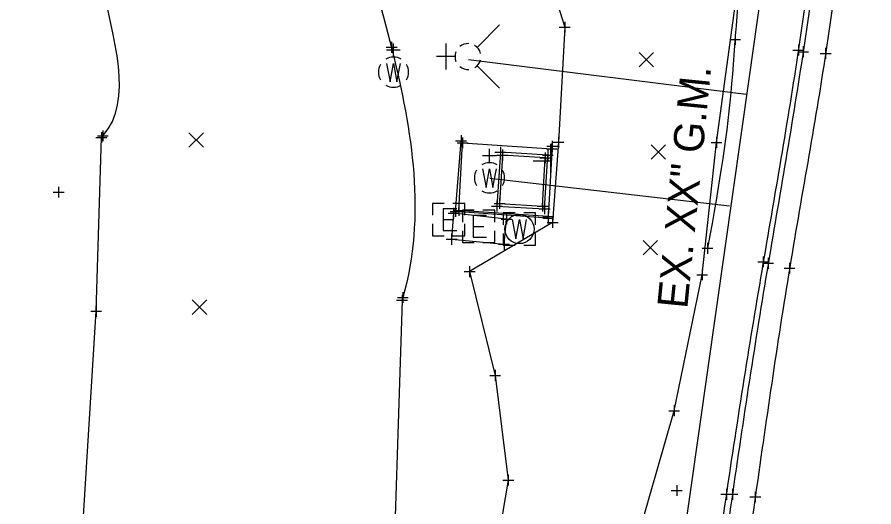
# Model space of a CAD drawing. Extents: x 1324089 to 1329959, y 459099 to 462017.
# Drawn here: x 1324630.8 to 1324710.1, y 459307.9 to 459353.2 of the extents above; entities that cross this region are included whole.
import ezdxf

# ---------------------------------------------------------------- set-up
doc = ezdxf.new("R2010")
doc.units = 0
for name, color, linetype in [('Default', 7, 'Continuous'), ('DR_X_Elev_Flow', 7, 'Continuous'), ('PM_X_Surveyed_Line', 7, 'Continuous'), ('PV_X_Curb', 7, 'Continuous'), ('PV_X_EOP', 7, 'Continuous'), ('RD_X_Concrete_Pad', 7, 'Continuous'), ('SN_X_Public', 7, 'Continuous'), ('SV_X_Break_Lines', 7, 'Continuous'), ('SV_X_Random_Point', 7, 'Continuous'), ('SV_X_Shot_Marker', 7, 'Continuous'), ('UT_X_Electric_Cells', 7, 'Continuous'), ('UT_X_Gas', 7, 'Continuous'), ('UT_X_Gas_Text', 7, 'Continuous'), ('UT_X_Water', 7, 'Continuous'), ('UT_X_Water_Cells', 7, 'Continuous')]:
    doc.layers.add(name, color=color, linetype=linetype)

msp = doc.modelspace()

# ---------------------------------------------------------------- linework, layer by layer
at = {"layer": 'Default'}
for points in [[(1324679.928, 459340.43), (1324675.526, 459340.713), (1324675.203, 459335.709), (1324679.624, 459335.463)], [(1324679.686, 459340.183), (1324675.715, 459340.448), (1324675.459, 459335.961), (1324679.444, 459335.727)]]:
    msp.add_lwpolyline(points, close=True, dxfattribs=at)
at = {"layer": 'DR_X_Elev_Flow'}
for p, q in [((1324634.62, 459337.501), (1324634.62, 459336.501)), ((1324634.12, 459337.001), (1324635.12, 459337.001)), ((1324634.62, 459337.001), (1324634.62, 459337.001))]:
    msp.add_line(p, q, dxfattribs=at)
at = {"layer": 'PM_X_Surveyed_Line'}
msp.add_open_spline([(1324720.827, 459365.006), (1324717.359, 459354.415), (1324715.896, 459334.744), (1324710.688, 459307.465), (1324707.684, 459283.27), (1324704.594, 459259.477), (1324702.801, 459238.335), (1324702.051, 459224.842), (1324701.816, 459219.293)], degree=3, dxfattribs=at)
at = {"layer": 'PV_X_Curb'}
for points in [[(1324554.609, 459526.256), (1324562.727, 459523.451), (1324573.614, 459507.995), (1324595.634, 459494.274), (1324618.058, 459478.412), (1324642.018, 459464.013), (1324665.498, 459452.566), (1324685.244, 459441.867), (1324699.443, 459427.92), (1324705.383, 459409.506), (1324706.272, 459390.25), (1324706.235, 459370.345), (1324703.79, 459350.238), (1324700.16, 459329.847), (1324696.79, 459308.111), (1324693.792, 459284.881), (1324690.959, 459260.876), (1324689.322, 459239.145), (1324688.41, 459225.434), (1324688.071, 459219.66)], [(1324554.405, 459525.774), (1324560.163, 459519.511), (1324574.45, 459509.18), (1324595.041, 459493.357), (1324617.898, 459478.11), (1324641.765, 459463.536), (1324665.205, 459452.03), (1324684.981, 459441.522), (1324698.948, 459427.624), (1324704.887, 459409.371), (1324705.692, 459390.232), (1324705.74, 459370.396), (1324703.348, 459350.363), (1324699.706, 459329.937), (1324696.22, 459308.214), (1324693.202, 459284.97), (1324690.537, 459260.981), (1324688.845, 459239.232), (1324687.9, 459225.509), (1324687.541, 459219.732)]]:
    msp.add_open_spline(points, degree=3, dxfattribs=at)
at = {"layer": 'PV_X_EOP'}
msp.add_open_spline([(1324556.157, 459527.565), (1324561.482, 459521.009), (1324576.429, 459511.53), (1324596.286, 459495.041), (1324619.321, 459480.244), (1324643.042, 459465.698), (1324666.449, 459454.069), (1324686.657, 459443.463), (1324700.989, 459428.912), (1324707.445, 459410.05), (1324708.191, 459390.355), (1324708.255, 459370.269), (1324705.916, 459350.006), (1324702.088, 459329.589), (1324698.992, 459307.797), (1324695.704, 459284.611), (1324693.286, 459260.576), (1324691.164, 459238.914), (1324690.346, 459225.303), (1324690.06, 459219.552)], degree=3, dxfattribs=at)
at = {"layer": 'RD_X_Concrete_Pad'}
for points in [[(1324679.966, 459334.754), (1324671.683, 459335.326), (1324672.034, 459341.579), (1324680.292, 459341.024), (1324680.315, 459341.259)], [(1324675.87, 459332.182), (1324676.096, 459334.51), (1324671.187, 459335.066), (1324671.016, 459332.644)]]:
    msp.add_lwpolyline(points, close=True, dxfattribs=at)
at = {"layer": 'SN_X_Public'}
for p, q in [((1324680.167, 459341.492), (1324680.167, 459338.292)), ((1324680.167, 459339.892), (1324678.567, 459339.892)), ((1324680.166, 459339.893), (1324680.166, 459339.893))]:
    msp.add_line(p, q, dxfattribs=at)
at = {"layer": 'SV_X_Break_Lines'}
for p, q in [((1324638.576, 459342.074), (1324638.714, 459342.227)), ((1324638.099, 459325.974), (1324638.576, 459342.074)), ((1324666.49, 459327.249), (1324666.423, 459327.011)), ((1324666.423, 459327.011), (1324665.662, 459303.052)), ((1324636.69, 459303.119), (1324638.099, 459325.974))]:
    msp.add_line(p, q, dxfattribs=at)
for points in [[(1324541.094, 459511.122), (1324561.978, 459492.743), (1324584.525, 459475.422), (1324605.248, 459461.382), (1324621.289, 459450.829), (1324632.107, 459444.104), (1324650.067, 459430.271), (1324666.204, 459410.058), (1324661.436, 459407.256), (1324665.741, 459392.416), (1324674.496, 459384.978), (1324677.71, 459376.688), (1324678.667, 459361.235), (1324681.487, 459352.293), (1324680.906, 459341.626), (1324680.368, 459334.206), (1324672.683, 459329.647), (1324675.043, 459320.041), (1324676.262, 459310.343), (1324675.179, 459303.964)], [(1324679.945, 459334.597), (1324671.367, 459335.214), (1324671.888, 459341.777)]]:
    msp.add_lwpolyline(points, dxfattribs=at)
for points in [[(1324640.512, 459459.521), (1324647.089, 459455.926), (1324657.022, 459448.614), (1324672.404, 459438.049), (1324688.497, 459430.408), (1324692.817, 459411.585), (1324698.272, 459395.281), (1324701.471, 459375.962), (1324697.719, 459361.699), (1324697.169, 459346.683), (1324695.905, 459338.224), (1324694.71, 459331.809)], [(1324562.077, 459396.515), (1324566.564, 459401.675), (1324579.241, 459409.429), (1324602.412, 459413.502), (1324625.669, 459407.067), (1324650.217, 459397.51), (1324658.543, 459372.548), (1324666.101, 459350.529), (1324668.645, 459334.822), (1324666.49, 459327.249)], [(1324638.714, 459342.227), (1324641.647, 459345.482), (1324637.721, 459357.192), (1324636.716, 459371.71), (1324623.652, 459387.374), (1324602.817, 459386.761), (1324580.6, 459381.005), (1324574.74, 459367.801), (1324573.351, 459359.374)]]:
    msp.add_open_spline(points, degree=3, dxfattribs=at)
at = {"layer": 'SV_X_Random_Point'}
for p, q in [((1324688.371, 459348.606), (1324689.704, 459349.941)), ((1324688.371, 459349.941), (1324689.704, 459348.606)), ((1324646.693, 459341.171), (1324648.026, 459342.506)), ((1324646.693, 459342.506), (1324648.026, 459341.171)), ((1324689.492, 459340.058), (1324690.825, 459341.393)), ((1324689.492, 459341.393), (1324690.825, 459340.058)), ((1324688.756, 459331.198), (1324690.089, 459332.533)), ((1324688.756, 459332.533), (1324690.089, 459331.198)), ((1324646.996, 459325.69), (1324648.33, 459327.025)), ((1324646.996, 459327.025), (1324648.33, 459325.69))]:
    msp.add_line(p, q, dxfattribs=at)
at = {"layer": 'SV_X_Shot_Marker'}
for p, q in [((1324681.487, 459352.793), (1324681.487, 459351.793)), ((1324680.987, 459352.293), (1324681.987, 459352.293)), ((1324681.487, 459352.293), (1324681.487, 459352.293)), ((1324697.279, 459351.654), (1324697.279, 459350.654)), ((1324665.457, 459350.929), (1324665.457, 459349.929)), ((1324696.779, 459351.154), (1324697.779, 459351.154)), ((1324697.279, 459351.154), (1324697.279, 459351.154)), ((1324664.957, 459350.429), (1324665.957, 459350.429)), ((1324665.457, 459350.429), (1324665.457, 459350.429)), ((1324702.622, 459350.166), (1324703.622, 459350.166)), ((1324703.122, 459350.666), (1324703.122, 459349.666)), ((1324703.122, 459350.166), (1324703.122, 459350.166)), ((1324703.569, 459350.519), (1324703.569, 459349.519)), ((1324705.651, 459350.362), (1324705.651, 459349.362)), ((1324703.069, 459350.019), (1324704.069, 459350.019)), ((1324703.569, 459350.019), (1324703.569, 459350.019)), ((1324705.151, 459349.862), (1324706.151, 459349.862)), ((1324705.651, 459349.862), (1324705.651, 459349.862)), ((1324638.214, 459342.227), (1324639.214, 459342.227)), ((1324638.576, 459342.574), (1324638.576, 459341.574)), ((1324638.714, 459342.727), (1324638.714, 459341.727)), ((1324638.714, 459342.227), (1324638.714, 459342.227)), ((1324671.888, 459342.277), (1324671.888, 459341.277)), ((1324680.906, 459342.126), (1324680.906, 459341.126)), ((1324695.549, 459342.119), (1324695.549, 459341.119)), ((1324638.076, 459342.074), (1324639.076, 459342.074)), ((1324638.576, 459342.074), (1324638.576, 459342.074)), ((1324671.388, 459341.777), (1324672.388, 459341.777)), ((1324671.534, 459341.579), (1324672.534, 459341.579)), ((1324671.888, 459341.777), (1324671.888, 459341.777)), ((1324672.034, 459342.079), (1324672.034, 459341.079)), ((1324672.034, 459341.579), (1324672.034, 459341.579)), ((1324680.292, 459341.524), (1324680.292, 459340.524)), ((1324680.315, 459341.759), (1324680.315, 459340.759)), ((1324680.406, 459341.626), (1324681.406, 459341.626)), ((1324680.906, 459341.626), (1324680.906, 459341.626)), ((1324695.049, 459341.619), (1324696.049, 459341.619)), ((1324695.549, 459341.619), (1324695.549, 459341.619)), ((1324675.026, 459340.713), (1324676.026, 459340.713)), ((1324675.526, 459341.213), (1324675.526, 459340.213)), ((1324675.526, 459340.713), (1324675.526, 459340.713)), ((1324675.715, 459340.948), (1324675.715, 459339.948)), ((1324679.686, 459340.683), (1324679.686, 459339.683)), ((1324679.792, 459341.024), (1324680.792, 459341.024)), ((1324679.815, 459341.259), (1324680.815, 459341.259)), ((1324679.928, 459340.93), (1324679.928, 459339.93)), ((1324680.292, 459341.024), (1324680.292, 459341.024)), ((1324680.315, 459341.259), (1324680.315, 459341.259)), ((1324675.215, 459340.448), (1324676.215, 459340.448)), ((1324675.715, 459340.448), (1324675.715, 459340.448)), ((1324679.186, 459340.183), (1324680.186, 459340.183)), ((1324679.428, 459340.43), (1324680.428, 459340.43)), ((1324679.686, 459340.183), (1324679.686, 459340.183)), ((1324679.928, 459340.43), (1324679.928, 459340.43)), ((1324671.683, 459335.826), (1324671.683, 459334.826)), ((1324674.959, 459335.961), (1324675.959, 459335.961)), ((1324675.203, 459336.209), (1324675.203, 459335.209)), ((1324675.459, 459336.461), (1324675.459, 459335.461)), ((1324675.459, 459335.961), (1324675.459, 459335.961)), ((1324679.444, 459336.227), (1324679.444, 459335.227)), ((1324679.624, 459335.963), (1324679.624, 459334.963)), ((1324670.687, 459335.066), (1324671.687, 459335.066)), ((1324670.867, 459335.214), (1324671.867, 459335.214)), ((1324671.183, 459335.326), (1324672.183, 459335.326)), ((1324671.187, 459335.566), (1324671.187, 459334.566)), ((1324671.187, 459335.066), (1324671.187, 459335.066)), ((1324671.367, 459335.714), (1324671.367, 459334.714)), ((1324671.367, 459335.214), (1324671.367, 459335.214)), ((1324671.683, 459335.326), (1324671.683, 459335.326)), ((1324674.703, 459335.709), (1324675.703, 459335.709)), ((1324675.203, 459335.709), (1324675.203, 459335.709)), ((1324676.096, 459335.01), (1324676.096, 459334.01)), ((1324678.944, 459335.727), (1324679.944, 459335.727)), ((1324679.124, 459335.463), (1324680.124, 459335.463)), ((1324679.444, 459335.727), (1324679.444, 459335.727)), ((1324679.624, 459335.463), (1324679.624, 459335.463)), ((1324679.945, 459335.097), (1324679.945, 459334.097)), ((1324679.966, 459335.254), (1324679.966, 459334.254)), ((1324675.596, 459334.51), (1324676.596, 459334.51)), ((1324676.096, 459334.51), (1324676.096, 459334.51)), ((1324679.445, 459334.597), (1324680.445, 459334.597)), ((1324679.466, 459334.754), (1324680.466, 459334.754)), ((1324679.868, 459334.206), (1324680.868, 459334.206)), ((1324679.945, 459334.597), (1324679.945, 459334.597)), ((1324679.966, 459334.754), (1324679.966, 459334.754)), ((1324680.368, 459334.706), (1324680.368, 459333.706)), ((1324680.368, 459334.206), (1324680.368, 459334.206)), ((1324670.516, 459332.644), (1324671.516, 459332.644)), ((1324671.016, 459333.144), (1324671.016, 459332.144)), ((1324671.016, 459332.644), (1324671.016, 459332.644)), ((1324675.87, 459332.682), (1324675.87, 459331.682)), ((1324675.37, 459332.182), (1324676.37, 459332.182)), ((1324675.87, 459332.182), (1324675.87, 459332.182)), ((1324694.21, 459331.809), (1324695.21, 459331.809)), ((1324694.71, 459332.309), (1324694.71, 459331.309)), ((1324694.71, 459331.809), (1324694.71, 459331.809)), ((1324699.873, 459331.064), (1324699.873, 459330.064)), ((1324699.373, 459330.564), (1324700.373, 459330.564)), ((1324699.834, 459330.419), (1324700.834, 459330.419)), ((1324699.873, 459330.564), (1324699.873, 459330.564)), ((1324700.334, 459330.919), (1324700.334, 459329.919)), ((1324700.334, 459330.419), (1324700.334, 459330.419)), ((1324702.307, 459330.474), (1324702.307, 459329.474)), ((1324672.183, 459329.647), (1324673.183, 459329.647)), ((1324672.683, 459330.147), (1324672.683, 459329.147)), ((1324672.683, 459329.647), (1324672.683, 459329.647)), ((1324694.222, 459329.849), (1324694.222, 459328.849)), ((1324701.807, 459329.974), (1324702.807, 459329.974)), ((1324702.307, 459329.974), (1324702.307, 459329.974)), ((1324693.722, 459329.349), (1324694.722, 459329.349)), ((1324694.222, 459329.349), (1324694.222, 459329.349)), ((1324665.99, 459327.249), (1324666.99, 459327.249)), ((1324666.423, 459327.511), (1324666.423, 459326.511)), ((1324666.49, 459327.749), (1324666.49, 459326.749)), ((1324666.49, 459327.249), (1324666.49, 459327.249)), ((1324638.099, 459326.474), (1324638.099, 459325.474)), ((1324665.923, 459327.011), (1324666.923, 459327.011)), ((1324666.423, 459327.011), (1324666.423, 459327.011)), ((1324637.599, 459325.974), (1324638.599, 459325.974)), ((1324638.099, 459325.974), (1324638.099, 459325.974)), ((1324674.543, 459320.041), (1324675.543, 459320.041)), ((1324675.043, 459320.541), (1324675.043, 459319.541)), ((1324675.043, 459320.041), (1324675.043, 459320.041)), ((1324691.131, 459316.77), (1324692.131, 459316.77)), ((1324691.631, 459317.27), (1324691.631, 459316.27)), ((1324691.631, 459316.77), (1324691.631, 459316.77)), ((1324676.262, 459310.843), (1324676.262, 459309.843)), ((1324675.762, 459310.343), (1324676.762, 459310.343)), ((1324676.262, 459310.343), (1324676.262, 459310.343)), ((1324691.858, 459309.884), (1324691.858, 459308.884)), ((1324691.858, 459309.884), (1324691.858, 459308.884)), ((1324691.358, 459309.384), (1324692.358, 459309.384)), ((1324691.358, 459309.384), (1324692.358, 459309.384)), ((1324691.858, 459309.384), (1324691.858, 459309.384)), ((1324691.858, 459309.384), (1324691.858, 459309.384)), ((1324695.954, 459309.025), (1324696.954, 459309.025)), ((1324696.454, 459309.525), (1324696.454, 459308.525)), ((1324696.454, 459309.025), (1324696.454, 459309.025)), ((1324696.519, 459309.026), (1324697.519, 459309.026)), ((1324697.019, 459309.526), (1324697.019, 459308.526)), ((1324697.019, 459309.026), (1324697.019, 459309.026)), ((1324698.635, 459308.796), (1324699.635, 459308.796)), ((1324699.135, 459309.296), (1324699.135, 459308.296)), ((1324699.135, 459308.796), (1324699.135, 459308.796))]:
    msp.add_line(p, q, dxfattribs=at)
at = {"layer": 'UT_X_Electric_Cells'}
for p, q in [((1324670.231, 459334.471), (1324671.231, 459334.471)), ((1324670.731, 459334.471), (1324670.731, 459334.471)), ((1324673.008, 459333.843), (1324674.008, 459333.843)), ((1324673.508, 459333.843), (1324673.508, 459333.843))]:
    msp.add_line(p, q, dxfattribs=at)
for points in [[(1324670.331, 459335.971), (1324669.231, 459335.971), (1324669.231, 459334.871)], [(1324672.231, 459334.871), (1324672.231, 459335.971), (1324671.131, 459335.971)], [(1324671.481, 459335.471), (1324670.231, 459335.471), (1324670.231, 459333.471), (1324671.481, 459333.471)], [(1324673.108, 459335.343), (1324672.008, 459335.343), (1324672.008, 459334.243)], [(1324675.008, 459334.243), (1324675.008, 459335.343), (1324673.908, 459335.343)], [(1324674.258, 459334.843), (1324673.008, 459334.843), (1324673.008, 459332.843), (1324674.258, 459332.843)], [(1324669.231, 459334.071), (1324669.231, 459332.971), (1324670.331, 459332.971)], [(1324671.131, 459332.971), (1324672.231, 459332.971), (1324672.231, 459334.071)], [(1324672.008, 459333.443), (1324672.008, 459332.343), (1324673.108, 459332.343)], [(1324673.908, 459332.343), (1324675.008, 459332.343), (1324675.008, 459333.443)]]:
    msp.add_lwpolyline(points, dxfattribs=at)
at = {"layer": 'UT_X_Gas'}
msp.add_lwpolyline([(1324679.129, 459219.684), (1324679.773, 459246.863), (1324682.585, 459269.573), (1324685.317, 459286.867), (1324687.693, 459303.105), (1324691.631, 459316.77), (1324694.222, 459329.349), (1324695.549, 459341.619), (1324697.277, 459354.269), (1324699.786, 459367.286)], dxfattribs=at)
at = {"layer": 'UT_X_Water'}
for p, q in [((1324672.58, 459349.292), (1324698.277, 459346.092)), ((1324674.552, 459338.304), (1324696.731, 459335.743))]:
    msp.add_line(p, q, dxfattribs=at)
msp.add_lwpolyline([(1324683.283, 459219.357), (1324691.61, 459298.587), (1324698.63, 459347.922), (1324699.63, 459354.943), (1324721.275, 459442.344), (1324756.062, 459540.186), (1324772.185, 459580.087), (1324802.339, 459646.278), (1324825.104, 459690.992), (1324841.263, 459722.731), (1324902.17, 459810.082), (1324917.22, 459828.862)], dxfattribs=at)
at = {"layer": 'UT_X_Water_Cells'}
for p, q in [((1324673.378, 459350.414), (1324675.457, 459352.494)), ((1324666.264, 459350.154), (1324664.992, 459350.154)), ((1324665.629, 459349.517), (1324665.629, 459350.789)), ((1324670.467, 459350.768), (1324670.467, 459348.368)), ((1324671.327, 459349.568), (1324669.607, 459349.568)), ((1324672.53, 459349.569), (1324672.53, 459349.569)), ((1324672.53, 459349.569), (1324672.53, 459349.569)), ((1324673.378, 459348.723), (1324675.457, 459346.643)), ((1324665.629, 459348.117), (1324665.629, 459348.117)), ((1324674.524, 459339.736), (1324674.524, 459341.008)), ((1324675.159, 459340.373), (1324673.887, 459340.373)), ((1324674.524, 459338.336), (1324674.524, 459338.336)), ((1324677.294, 459333.593), (1324677.294, 459333.593))]:
    msp.add_line(p, q, dxfattribs=at)
for points in [[(1324664.992, 459348.937), (1324665.31, 459347.214), (1324665.629, 459348.937), (1324665.949, 459347.214), (1324666.265, 459348.937)], [(1324673.887, 459339.156), (1324674.206, 459337.433), (1324674.524, 459339.156), (1324674.844, 459337.433), (1324675.161, 459339.156)], [(1324676.894, 459335.093), (1324675.794, 459335.093), (1324675.794, 459333.993)], [(1324678.794, 459333.993), (1324678.794, 459335.093), (1324677.694, 459335.093)], [(1324676.627, 459334.493), (1324676.96, 459332.693), (1324677.294, 459334.493), (1324677.627, 459332.693), (1324677.96, 459334.493)], [(1324675.794, 459333.193), (1324675.794, 459332.093), (1324676.894, 459332.093)], [(1324677.694, 459332.093), (1324678.794, 459332.093), (1324678.794, 459333.193)]]:
    msp.add_lwpolyline(points, dxfattribs=at)
msp.add_circle((1324677.294, 459333.593), 1.35, dxfattribs=at)
for centre, radius, start, end in [((1324672.53, 459349.569), 1.2, 86.01648, 129.98885), ((1324672.53, 459349.569), 1.2, 13.82389, 59.90967), ((1324665.628, 459348.119), 1.4, 60.01836, 120.01574), ((1324672.53, 459349.569), 1.2, 158.13946, 202.03798), ((1324672.53, 459349.569), 1.2, 301.87877, 345.84793), ((1324665.628, 459348.119), 1.4, 150.01836, 209.98164), ((1324665.628, 459348.119), 1.4, 330.01836, 29.98164), ((1324672.53, 459349.569), 1.2, 230.02099, 274.06293), ((1324665.628, 459348.119), 1.4, 239.98426, 299.98164), ((1324674.524, 459338.338), 1.4, 60.01836, 120.01574), ((1324674.524, 459338.338), 1.4, 150.01836, 209.98164), ((1324674.524, 459338.338), 1.4, 330.01836, 29.98164), ((1324674.524, 459338.338), 1.4, 239.98426, 299.98164)]:
    msp.add_arc(centre, radius, start, end, dxfattribs=at)

# ---------------------------------------------------------------- texts
at = {"layer": 'UT_X_Gas_Text'}
msp.add_text('EX. XX" G.M.', height=2.8, rotation=84.33299, dxfattribs=at).set_placement((1324692.831, 459326.152))

doc.saveas('drawing.dxf')
